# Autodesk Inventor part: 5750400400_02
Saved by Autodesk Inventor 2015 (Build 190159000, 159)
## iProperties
Created: 2020-07
Part Number: 5750400400_02
Checked By: TraceParts S.A.
Material: Generic
Catalog Web Link: www.traceparts.com
Document SubType Name: Modeling
Designer: TraceParts
Density: 1 g/cm^3
Appearance: Default
Company: TraceParts S.A.
Author: TraceParts
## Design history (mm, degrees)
feature "5750400400_02.ipt"
body "Solid1"
